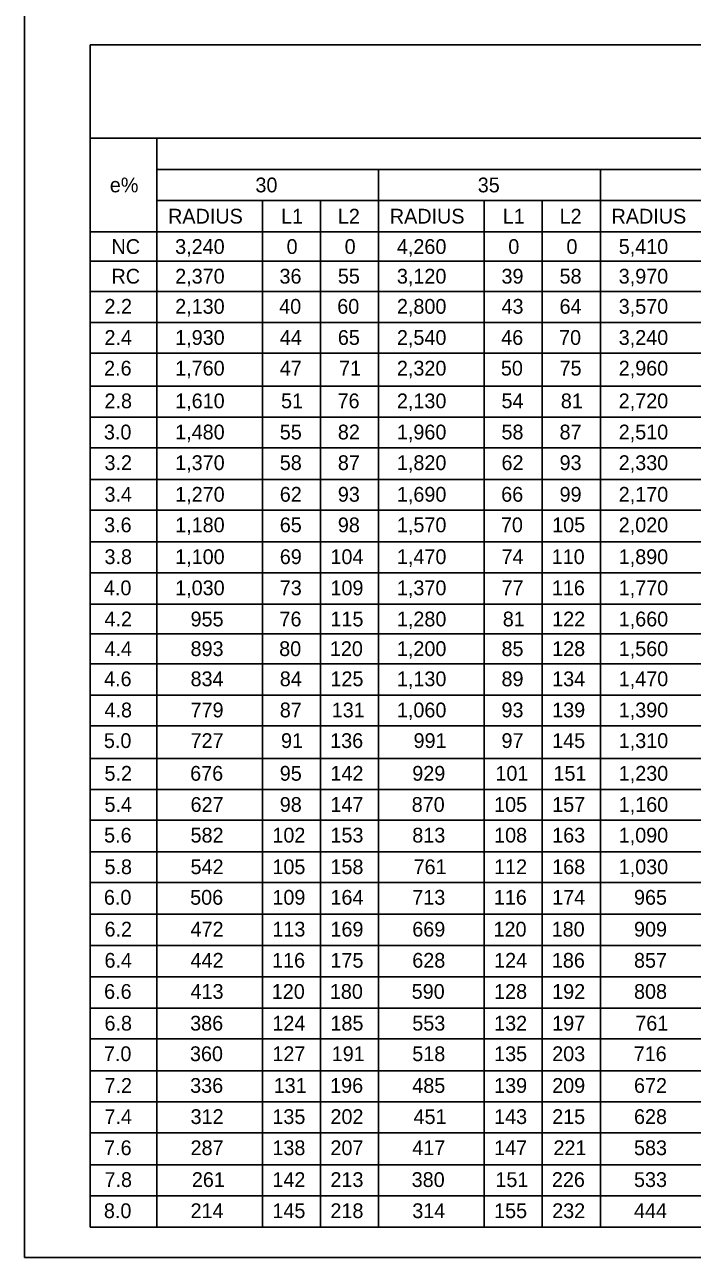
# Model space of a CAD drawing. Extents: x -404.8 to -373.6, y -458.1 to -437.7.
# Drawn here: x -404.83 to -398.05, y -458.05 to -445.54 of the extents above; entities that cross this region are included whole.
import ezdxf

# ---------------------------------------------------------------- set-up
doc = ezdxf.new("R2010")
doc.units = 0
for name, color, linetype in [('Bridge-Named Boundary', 7, 'Continuous'), ('Common-Notes', 7, 'Continuous'), ('Level 4', 7, 'Continuous')]:
    doc.layers.add(name, color=color, linetype=linetype)

msp = doc.modelspace()

# ---------------------------------------------------------------- linework, layer by layer
at = {"layer": 'Bridge-Named Boundary'}
msp.add_lwpolyline([(-404.826, -458.051), (-373.576, -458.051), (-373.576, -437.676), (-404.826, -437.676)], close=True, dxfattribs=at)
at = {"layer": 'Level 4'}
for p, q in [((-404.161, -445.747), (-383.242, -445.747)), ((-404.161, -445.747), (-404.161, -457.744)), ((-404.161, -446.696), (-383.242, -446.696)), ((-403.485, -446.696), (-403.485, -457.744)), ((-403.485, -447.012), (-383.242, -447.012)), ((-401.236, -447.012), (-401.236, -457.744)), ((-398.986, -447.012), (-398.986, -457.744)), ((-403.485, -447.328), (-383.242, -447.328)), ((-402.414, -447.328), (-402.414, -457.744)), ((-401.825, -447.328), (-401.825, -457.744)), ((-400.165, -447.328), (-400.165, -457.744)), ((-399.576, -447.328), (-399.576, -457.744)), ((-404.161, -447.645), (-383.242, -447.645)), ((-404.161, -447.945), (-383.242, -447.945)), ((-404.161, -448.251), (-383.242, -448.251)), ((-404.161, -448.567), (-383.242, -448.567)), ((-404.161, -448.878), (-383.242, -448.878)), ((-404.161, -449.21), (-383.242, -449.21)), ((-404.161, -449.526), (-383.242, -449.526)), ((-404.161, -449.837), (-383.242, -449.837)), ((-404.161, -450.159), (-383.242, -450.159)), ((-404.161, -450.469), (-383.242, -450.469)), ((-404.161, -450.791), (-383.242, -450.791)), ((-404.161, -451.107), (-383.242, -451.107)), ((-404.161, -451.424), (-383.242, -451.424)), ((-404.161, -451.724), (-383.242, -451.724)), ((-404.161, -452.03), (-383.242, -452.03)), ((-404.161, -452.346), (-383.242, -452.346)), ((-404.161, -452.657), (-383.242, -452.657)), ((-404.161, -452.989), (-383.242, -452.989)), ((-404.161, -453.305), (-383.242, -453.305)), ((-404.161, -453.616), (-383.242, -453.616)), ((-404.161, -453.938), (-383.242, -453.938)), ((-404.161, -454.248), (-383.242, -454.248)), ((-404.161, -454.57), (-383.242, -454.57)), ((-404.161, -454.886), (-383.242, -454.886)), ((-404.161, -455.203), (-383.242, -455.203)), ((-404.161, -455.524), (-383.242, -455.524)), ((-404.161, -455.834), (-383.242, -455.834)), ((-404.161, -456.157), (-383.242, -456.157)), ((-404.161, -456.473), (-383.242, -456.473)), ((-404.161, -456.789), (-383.242, -456.789)), ((-404.161, -457.111), (-383.242, -457.111)), ((-404.161, -457.427), (-383.242, -457.427)), ((-404.161, -457.744), (-383.242, -457.744))]:
    msp.add_line(p, q, dxfattribs=at)

# ---------------------------------------------------------------- texts
at = {"layer": 'Common-Notes'}
for s, p in [('e%', (-403.962, -447.245)), ('30', (-402.485, -447.245)), ('35', (-400.23, -447.245)), ('RADIUS', (-403.371, -447.562)), ('L1', (-402.225, -447.562)), ('L2', (-401.649, -447.562)), ('RADIUS', (-401.122, -447.562)), ('L1', (-399.976, -447.562)), ('L2', (-399.4, -447.562)), ('RADIUS', (-398.873, -447.562)), ('NC', (-403.945, -447.87)), ('3,240', (-403.299, -447.87)), ('0', (-402.169, -447.87)), ('0', (-401.58, -447.87)), ('4,260', (-401.05, -447.87)), ('0', (-399.92, -447.87)), ('0', (-399.33, -447.87)), ('5,410', (-398.8, -447.87)), ('RC', (-403.945, -448.171)), ('2,370', (-403.299, -448.171)), ('36', (-402.241, -448.171)), ('55', (-401.649, -448.171)), ('3,120', (-401.05, -448.171)), ('39', (-399.989, -448.171)), ('58', (-399.4, -448.171)), ('3,970', (-398.8, -448.171)), ('2.2', (-404.016, -448.477)), ('2,130', (-403.299, -448.477)), ('40', (-402.244, -448.477)), ('60', (-401.655, -448.477)), ('2,800', (-401.05, -448.477)), ('43', (-399.989, -448.477)), ('64', (-399.4, -448.477)), ('3,570', (-398.8, -448.477)), ('2.4', (-404.016, -448.793)), ('1,930', (-403.299, -448.793)), ('44', (-402.238, -448.793)), ('65', (-401.649, -448.793)), ('2,540', (-401.05, -448.793)), ('46', (-399.992, -448.793)), ('70', (-399.405, -448.793)), ('3,240', (-398.8, -448.793)), ('2.6', (-404.02, -449.104)), ('1,760', (-403.299, -449.104)), ('47', (-402.238, -449.104)), ('71', (-401.636, -449.104)), ('2,320', (-401.05, -449.104)), ('50', (-399.995, -449.104)), ('75', (-399.4, -449.104)), ('2,960', (-398.8, -449.104)), ('2.8', (-404.016, -449.436)), ('1,610', (-403.299, -449.436)), ('51', (-402.225, -449.436)), ('76', (-401.652, -449.436)), ('2,130', (-401.05, -449.436)), ('54', (-399.989, -449.436)), ('81', (-399.387, -449.436)), ('2,720', (-398.8, -449.436)), ('3.0', (-404.022, -449.752)), ('1,480', (-403.299, -449.752)), ('55', (-402.238, -449.752)), ('82', (-401.649, -449.752)), ('1,960', (-401.05, -449.752)), ('58', (-399.989, -449.752)), ('87', (-399.4, -449.752)), ('2,510', (-398.8, -449.752)), ('3.2', (-404.016, -450.063)), ('1,370', (-403.299, -450.063)), ('58', (-402.238, -450.063)), ('87', (-401.649, -450.063)), ('1,820', (-401.05, -450.063)), ('62', (-399.989, -450.063)), ('93', (-399.4, -450.063)), ('2,330', (-398.8, -450.063)), ('3.4', (-404.016, -450.384)), ('1,270', (-403.299, -450.384)), ('62', (-402.238, -450.384)), ('93', (-401.649, -450.384)), ('1,690', (-401.05, -450.384)), ('66', (-399.992, -450.384)), ('99', (-399.4, -450.384)), ('2,170', (-398.8, -450.384)), ('3.6', (-404.02, -450.694)), ('1,180', (-403.299, -450.694)), ('65', (-402.238, -450.694)), ('98', (-401.649, -450.694)), ('1,570', (-401.05, -450.694)), ('70', (-399.995, -450.694)), ('105', (-399.475, -450.694)), ('2,020', (-398.8, -450.694)), ('3.8', (-404.016, -451.017)), ('1,100', (-403.299, -451.017)), ('69', (-402.238, -451.017)), ('104', (-401.724, -451.017)), ('1,470', (-401.05, -451.017)), ('74', (-399.989, -451.017)), ('110', (-399.48, -451.017)), ('1,890', (-398.8, -451.017)), ('4.0', (-404.022, -451.333)), ('1,030', (-403.299, -451.333)), ('73', (-402.238, -451.333)), ('109', (-401.724, -451.333)), ('1,370', (-401.05, -451.333)), ('77', (-399.989, -451.333)), ('116', (-399.478, -451.333)), ('1,770', (-398.8, -451.333)), ('4.2', (-404.016, -451.649)), ('955', (-403.143, -451.649)), ('76', (-402.241, -451.649)), ('115', (-401.724, -451.649)), ('1,280', (-401.05, -451.649)), ('81', (-399.976, -451.649)), ('122', (-399.475, -451.649)), ('1,660', (-398.8, -451.649)), ('4.4', (-404.016, -451.95)), ('893', (-403.143, -451.95)), ('80', (-402.244, -451.95)), ('120', (-401.73, -451.95)), ('1,200', (-401.05, -451.95)), ('85', (-399.989, -451.95)), ('128', (-399.475, -451.95)), ('1,560', (-398.8, -451.95)), ('4.6', (-404.02, -452.256)), ('834', (-403.143, -452.256)), ('84', (-402.238, -452.256)), ('125', (-401.724, -452.256)), ('1,130', (-401.05, -452.256)), ('89', (-399.989, -452.256)), ('134', (-399.475, -452.256)), ('1,470', (-398.8, -452.256)), ('4.8', (-404.016, -452.572)), ('779', (-403.143, -452.572)), ('87', (-402.238, -452.572)), ('131', (-401.711, -452.572)), ('1,060', (-401.05, -452.572)), ('93', (-399.989, -452.572)), ('139', (-399.475, -452.572)), ('1,390', (-398.8, -452.572)), ('5.0', (-404.022, -452.883)), ('727', (-403.143, -452.883)), ('91', (-402.225, -452.883)), ('136', (-401.727, -452.883)), ('991', (-400.881, -452.883)), ('97', (-399.989, -452.883)), ('145', (-399.475, -452.883)), ('1,310', (-398.8, -452.883)), ('5.2', (-404.016, -453.215)), ('676', (-403.147, -453.215)), ('95', (-402.238, -453.215)), ('142', (-401.724, -453.215)), ('929', (-400.894, -453.215)), ('101', (-400.051, -453.215)), ('151', (-399.462, -453.215)), ('1,230', (-398.8, -453.215)), ('5.4', (-404.016, -453.531)), ('627', (-403.143, -453.531)), ('98', (-402.238, -453.531)), ('147', (-401.724, -453.531)), ('870', (-400.9, -453.531)), ('105', (-400.064, -453.531)), ('157', (-399.475, -453.531)), ('1,160', (-398.8, -453.531)), ('5.6', (-404.02, -453.842)), ('582', (-403.143, -453.842)), ('102', (-402.313, -453.842)), ('153', (-401.724, -453.842)), ('813', (-400.894, -453.842)), ('108', (-400.064, -453.842)), ('163', (-399.475, -453.842)), ('1,090', (-398.8, -453.842)), ('5.8', (-404.016, -454.163)), ('542', (-403.143, -454.163)), ('105', (-402.313, -454.163)), ('158', (-401.724, -454.163)), ('761', (-400.881, -454.163)), ('112', (-400.064, -454.163)), ('168', (-399.475, -454.163)), ('1,030', (-398.8, -454.163)), ('6.0', (-404.022, -454.473)), ('506', (-403.147, -454.473)), ('109', (-402.313, -454.473)), ('164', (-401.724, -454.473)), ('713', (-400.894, -454.473)), ('116', (-400.067, -454.473)), ('174', (-399.475, -454.473)), ('965', (-398.645, -454.473)), ('6.2', (-404.016, -454.796)), ('472', (-403.143, -454.796)), ('113', (-402.313, -454.796)), ('169', (-401.724, -454.796)), ('669', (-400.894, -454.796)), ('120', (-400.07, -454.796)), ('180', (-399.48, -454.796)), ('909', (-398.645, -454.796)), ('6.4', (-404.016, -455.112)), ('442', (-403.143, -455.112)), ('116', (-402.316, -455.112)), ('175', (-401.724, -455.112)), ('628', (-400.894, -455.112)), ('124', (-400.064, -455.112)), ('186', (-399.478, -455.112)), ('857', (-398.645, -455.112)), ('6.6', (-404.02, -455.428)), ('413', (-403.143, -455.428)), ('120', (-402.319, -455.428)), ('180', (-401.73, -455.428)), ('590', (-400.9, -455.428)), ('128', (-400.064, -455.428)), ('192', (-399.475, -455.428)), ('808', (-398.645, -455.428)), ('6.8', (-404.016, -455.75)), ('386', (-403.147, -455.75)), ('124', (-402.313, -455.75)), ('185', (-401.724, -455.75)), ('553', (-400.894, -455.75)), ('132', (-400.064, -455.75)), ('197', (-399.475, -455.75)), ('761', (-398.632, -455.75)), ('7.0', (-404.022, -456.06)), ('360', (-403.149, -456.06)), ('127', (-402.313, -456.06)), ('191', (-401.711, -456.06)), ('518', (-400.894, -456.06)), ('135', (-400.064, -456.06)), ('203', (-399.475, -456.06)), ('716', (-398.648, -456.06)), ('7.2', (-404.016, -456.382)), ('336', (-403.147, -456.382)), ('131', (-402.3, -456.382)), ('196', (-401.727, -456.382)), ('485', (-400.894, -456.382)), ('139', (-400.064, -456.382)), ('209', (-399.475, -456.382)), ('672', (-398.645, -456.382)), ('7.4', (-404.016, -456.698)), ('312', (-403.143, -456.698)), ('135', (-402.313, -456.698)), ('202', (-401.724, -456.698)), ('451', (-400.881, -456.698)), ('143', (-400.064, -456.698)), ('215', (-399.475, -456.698)), ('628', (-398.645, -456.698)), ('7.6', (-404.02, -457.014)), ('287', (-403.143, -457.014)), ('138', (-402.313, -457.014)), ('207', (-401.724, -457.014)), ('417', (-400.894, -457.014)), ('147', (-400.064, -457.014)), ('221', (-399.462, -457.014)), ('583', (-398.645, -457.014)), ('7.8', (-404.016, -457.337)), ('261', (-403.13, -457.337)), ('142', (-402.313, -457.337)), ('213', (-401.724, -457.337)), ('380', (-400.9, -457.337)), ('151', (-400.051, -457.337)), ('226', (-399.478, -457.337)), ('533', (-398.645, -457.337)), ('8.0', (-404.022, -457.653)), ('214', (-403.143, -457.653)), ('145', (-402.313, -457.653)), ('218', (-401.724, -457.653)), ('314', (-400.894, -457.653)), ('155', (-400.064, -457.653)), ('232', (-399.475, -457.653)), ('444', (-398.645, -457.653))]:
    msp.add_text(s, height=0.15, dxfattribs=at).set_placement(p)

doc.saveas('drawing.dxf')
